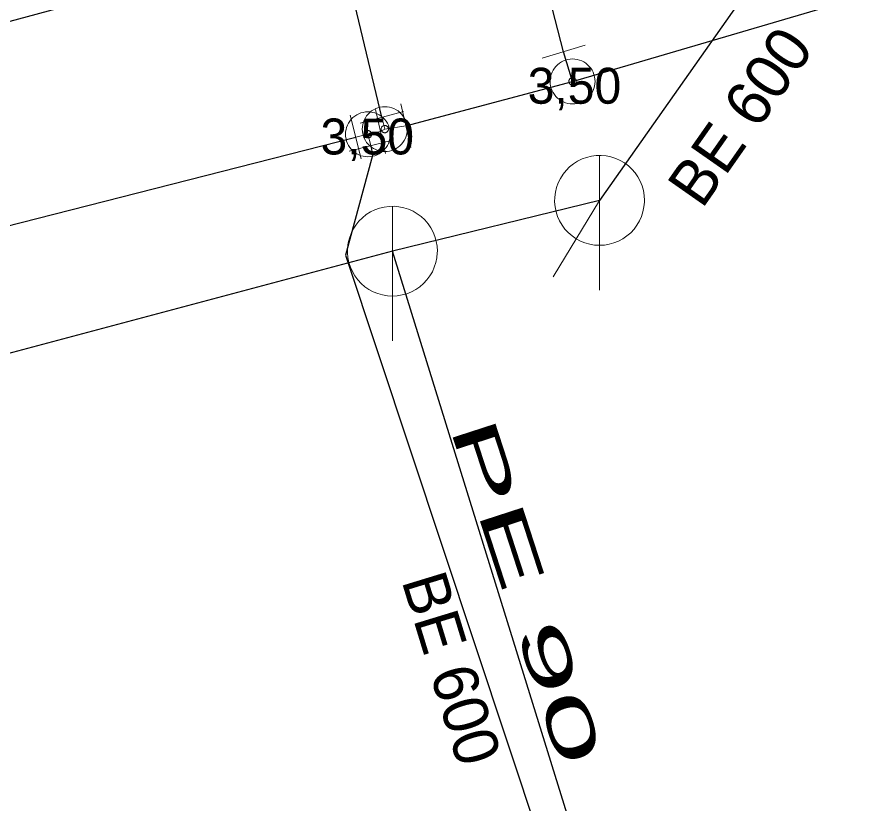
# Model space of a CAD drawing. Extents: x -682839 to -682312, y -994645 to -993949.
# Drawn here: x -682717.39 to -682698.3, y -994094.48 to -994076.96 of the extents above; entities that cross this region are included whole.
import ezdxf

# ---------------------------------------------------------------- set-up
doc = ezdxf.new("R2010")
doc.units = 0
doc.header["$LTSCALE"] = 0.4
doc.layers.add('1', color=7, linetype='Continuous')
for name, color, linetype, lineweight in [('11', 7, 'Continuous', 13), ('14', 7, 'Continuous', 25), ('17', 7, 'Continuous', 25), ('22', 7, 'Continuous', 13), ('34', 7, 'Continuous', 13), ('47', 7, 'Continuous', 13)]:
    doc.layers.add(name, color=color, linetype=linetype, lineweight=lineweight)

msp = doc.modelspace()

# ---------------------------------------------------------------- linework, layer by layer
at = {"layer": '11'}
msp.add_line((-682705.46, -994082.739), (-682704.43, -994081.039), dxfattribs=at)
at = {"layer": '14'}
for p, q in [((-682699.67, -994074.27), (-682704.43, -994081.039)), ((-682704.43, -994081.039), (-682709.039, -994082.17)), ((-682709.039, -994082.17), (-682748.64, -994092.739)), ((-682703.07, -994101.399), (-682709.039, -994082.17))]:
    msp.add_line(p, q, dxfattribs=at)
at = {"layer": '14', "lineweight": 13}
for p, q in [((-682709.208, -994079.453), (-682708.739, -994079.377)), ((-682709.583, -994079.568), (-682709.519, -994079.82))]:
    msp.add_line(p, q, dxfattribs=at)
msp.add_lwpolyline([(-682709.855, -994079.629), (-682709.583, -994079.568), (-682709.307, -994079.505), (-682709.208, -994079.453), (-682709.273, -994079.188)], dxfattribs=at)
at = {"layer": '17'}
for p, q in [((-682705.23, -994077.73), (-682706.989, -994070.899)), ((-682709.273, -994079.188), (-682710.75, -994073.01)), ((-682705.03, -994078.39), (-682705.23, -994077.73)), ((-682708.739, -994079.377), (-682705.03, -994078.39))]:
    msp.add_line(p, q, dxfattribs=at)
for points in [[(-682473.55, -994045.57), (-682522.289, -994043.899), (-682529.616, -994044.905), (-682556.26, -994048.129), (-682661.506, -994061.932), (-682719.074, -994077.464), (-682816.699, -994104.109)], [(-682705.03, -994078.39), (-682696.77, -994075.96), (-682691.829, -994074.544), (-682685.35, -994072.597), (-682672.05, -994068.67), (-682644.92, -994063.19), (-682632.77, -994060.73)], [(-682788.97, -994100.714), (-682780.37, -994098.68), (-682746.43, -994089.07), (-682728.02, -994084.32), (-682718.061, -994081.728), (-682709.855, -994079.629)], [(-682709.519, -994079.82), (-682709.48, -994080.039), (-682710.079, -994082.26), (-682705.76, -994095.289), (-682710, -994096.699)]]:
    msp.add_lwpolyline(points, dxfattribs=at)
at = {"layer": '22'}
for p, q in [((-682704.43, -994083.039), (-682704.429, -994080.039)), ((-682709.039, -994084.17), (-682709.038, -994081.17))]:
    msp.add_line(p, q, dxfattribs=at)
for points in [[(-682703.43, -994081.039), (-682703.435, -994080.93), (-682703.453, -994080.822), (-682703.483, -994080.716), (-682703.523, -994080.615), (-682703.575, -994080.518), (-682703.637, -994080.428), (-682703.709, -994080.345), (-682703.789, -994080.271), (-682703.877, -994080.205), (-682703.971, -994080.15), (-682704.071, -994080.105), (-682704.176, -994080.072), (-682704.283, -994080.05), (-682704.392, -994080.04), (-682704.502, -994080.042), (-682704.61, -994080.056), (-682704.717, -994080.081), (-682704.82, -994080.118), (-682704.918, -994080.167), (-682705.01, -994080.225), (-682705.096, -994080.294), (-682705.173, -994080.371), (-682705.242, -994080.457), (-682705.301, -994080.549), (-682705.349, -994080.647), (-682705.386, -994080.75), (-682705.412, -994080.857), (-682705.426, -994080.965), (-682705.429, -994081.075), (-682705.419, -994081.184), (-682705.398, -994081.291), (-682705.364, -994081.395), (-682705.32, -994081.495), (-682705.265, -994081.59), (-682705.199, -994081.678), (-682705.125, -994081.758), (-682705.042, -994081.83), (-682704.952, -994081.892), (-682704.856, -994081.944), (-682704.754, -994081.985), (-682704.649, -994082.015), (-682704.541, -994082.033), (-682704.431, -994082.039), (-682704.322, -994082.033), (-682704.214, -994082.015), (-682704.109, -994081.986), (-682704.007, -994081.945), (-682703.91, -994081.893), (-682703.82, -994081.831), (-682703.737, -994081.76), (-682703.662, -994081.68), (-682703.597, -994081.592), (-682703.541, -994081.498), (-682703.497, -994081.398), (-682703.463, -994081.294), (-682703.441, -994081.186), (-682703.431, -994081.077)], [(-682708.039, -994082.17), (-682708.044, -994082.061), (-682708.062, -994081.953), (-682708.092, -994081.847), (-682708.132, -994081.746), (-682708.184, -994081.649), (-682708.246, -994081.559), (-682708.318, -994081.476), (-682708.398, -994081.402), (-682708.486, -994081.336), (-682708.58, -994081.281), (-682708.68, -994081.236), (-682708.785, -994081.203), (-682708.892, -994081.181), (-682709.001, -994081.171), (-682709.111, -994081.173), (-682709.219, -994081.187), (-682709.326, -994081.212), (-682709.429, -994081.249), (-682709.527, -994081.298), (-682709.619, -994081.356), (-682709.705, -994081.425), (-682709.782, -994081.502), (-682709.851, -994081.588), (-682709.91, -994081.68), (-682709.958, -994081.778), (-682709.995, -994081.881), (-682710.021, -994081.988), (-682710.035, -994082.096), (-682710.038, -994082.206), (-682710.028, -994082.315), (-682710.007, -994082.422), (-682709.973, -994082.526), (-682709.929, -994082.626), (-682709.874, -994082.721), (-682709.808, -994082.809), (-682709.734, -994082.889), (-682709.651, -994082.961), (-682709.561, -994083.023), (-682709.465, -994083.075), (-682709.363, -994083.116), (-682709.258, -994083.146), (-682709.15, -994083.164), (-682709.04, -994083.17), (-682708.931, -994083.164), (-682708.823, -994083.146), (-682708.718, -994083.117), (-682708.616, -994083.076), (-682708.519, -994083.024), (-682708.429, -994082.962), (-682708.346, -994082.891), (-682708.271, -994082.811), (-682708.206, -994082.723), (-682708.15, -994082.629), (-682708.106, -994082.529), (-682708.072, -994082.425), (-682708.05, -994082.317), (-682708.04, -994082.208)]]:
    msp.add_lwpolyline(points, close=True, dxfattribs=at)
at = {"layer": '34'}
for p, q in [((-682705.708, -994077.875), (-682704.751, -994077.585)), ((-682708.85, -994078.889), (-682708.628, -994079.864)), ((-682708.79, -994079.057), (-682709.755, -994079.317)), ((-682709.418, -994079.017), (-682709.196, -994079.992)), ((-682709.979, -994079.144), (-682709.731, -994080.113)), ((-682709.034, -994079.696), (-682710.003, -994079.942))]:
    msp.add_line(p, q, dxfattribs=at)
at = {"layer": '47'}
for points in [[(-682704.53, -994078.39), (-682704.533, -994078.338), (-682704.541, -994078.286), (-682704.555, -994078.236), (-682704.573, -994078.187), (-682704.597, -994078.14), (-682704.626, -994078.096), (-682704.659, -994078.056), (-682704.696, -994078.019), (-682704.736, -994077.986), (-682704.78, -994077.957), (-682704.827, -994077.933), (-682704.876, -994077.915), (-682704.926, -994077.901), (-682704.978, -994077.893), (-682705.03, -994077.89), (-682705.082, -994077.893), (-682705.134, -994077.901), (-682705.185, -994077.915), (-682705.233, -994077.933), (-682705.28, -994077.957), (-682705.324, -994077.986), (-682705.365, -994078.019), (-682705.402, -994078.056), (-682705.435, -994078.096), (-682705.463, -994078.14), (-682705.487, -994078.187), (-682705.506, -994078.236), (-682705.519, -994078.286), (-682705.527, -994078.338), (-682705.53, -994078.39), (-682705.527, -994078.442), (-682705.519, -994078.494), (-682705.506, -994078.545), (-682705.487, -994078.593), (-682705.463, -994078.64), (-682705.435, -994078.684), (-682705.402, -994078.725), (-682705.365, -994078.762), (-682705.324, -994078.795), (-682705.28, -994078.823), (-682705.233, -994078.847), (-682705.185, -994078.866), (-682705.134, -994078.879), (-682705.082, -994078.887), (-682705.03, -994078.89), (-682704.978, -994078.887), (-682704.926, -994078.879), (-682704.876, -994078.866), (-682704.827, -994078.847), (-682704.78, -994078.823), (-682704.736, -994078.795), (-682704.696, -994078.762), (-682704.659, -994078.725), (-682704.626, -994078.684), (-682704.597, -994078.64), (-682704.573, -994078.593), (-682704.555, -994078.545), (-682704.541, -994078.494), (-682704.533, -994078.442)], [(-682704.948, -994078.39), (-682704.948, -994078.381), (-682704.95, -994078.373), (-682704.952, -994078.365), (-682704.955, -994078.357), (-682704.959, -994078.349), (-682704.964, -994078.342), (-682704.969, -994078.335), (-682704.975, -994078.329), (-682704.982, -994078.324), (-682704.989, -994078.319), (-682704.997, -994078.315), (-682705.005, -994078.312), (-682705.013, -994078.31), (-682705.021, -994078.308), (-682705.03, -994078.308), (-682705.039, -994078.308), (-682705.047, -994078.31), (-682705.055, -994078.312), (-682705.063, -994078.315), (-682705.071, -994078.319), (-682705.078, -994078.324), (-682705.085, -994078.329), (-682705.091, -994078.335), (-682705.097, -994078.342), (-682705.101, -994078.349), (-682705.105, -994078.357), (-682705.108, -994078.365), (-682705.11, -994078.373), (-682705.112, -994078.381), (-682705.112, -994078.39), (-682705.112, -994078.399), (-682705.11, -994078.407), (-682705.108, -994078.415), (-682705.105, -994078.423), (-682705.101, -994078.431), (-682705.097, -994078.438), (-682705.091, -994078.445), (-682705.085, -994078.451), (-682705.078, -994078.457), (-682705.071, -994078.461), (-682705.063, -994078.465), (-682705.055, -994078.468), (-682705.047, -994078.47), (-682705.039, -994078.472), (-682705.03, -994078.472), (-682705.021, -994078.472), (-682705.013, -994078.47), (-682705.005, -994078.468), (-682704.997, -994078.465), (-682704.989, -994078.461), (-682704.982, -994078.457), (-682704.975, -994078.451), (-682704.969, -994078.445), (-682704.964, -994078.438), (-682704.959, -994078.431), (-682704.955, -994078.423), (-682704.952, -994078.415), (-682704.95, -994078.407), (-682704.948, -994078.399)], [(-682709.083, -994079.568), (-682709.086, -994079.516), (-682709.094, -994079.463), (-682709.108, -994079.414), (-682709.125, -994079.365), (-682709.15, -994079.318), (-682709.179, -994079.274), (-682709.212, -994079.233), (-682709.249, -994079.196), (-682709.289, -994079.164), (-682709.333, -994079.135), (-682709.38, -994079.11), (-682709.429, -994079.093), (-682709.478, -994079.079), (-682709.531, -994079.071), (-682709.583, -994079.068), (-682709.635, -994079.071), (-682709.687, -994079.079), (-682709.738, -994079.093), (-682709.786, -994079.11), (-682709.833, -994079.135), (-682709.877, -994079.164), (-682709.918, -994079.196), (-682709.955, -994079.233), (-682709.988, -994079.274), (-682710.016, -994079.318), (-682710.04, -994079.365), (-682710.059, -994079.414), (-682710.071, -994079.463), (-682710.08, -994079.516), (-682710.083, -994079.568), (-682710.08, -994079.62), (-682710.071, -994079.672), (-682710.059, -994079.723), (-682710.04, -994079.771), (-682710.016, -994079.818), (-682709.988, -994079.862), (-682709.955, -994079.902), (-682709.918, -994079.94), (-682709.877, -994079.973), (-682709.833, -994080), (-682709.786, -994080.025), (-682709.738, -994080.044), (-682709.687, -994080.056), (-682709.635, -994080.065), (-682709.583, -994080.068), (-682709.531, -994080.065), (-682709.478, -994080.056), (-682709.429, -994080.044), (-682709.38, -994080.025), (-682709.333, -994080), (-682709.289, -994079.973), (-682709.249, -994079.94), (-682709.212, -994079.902), (-682709.179, -994079.862), (-682709.15, -994079.818), (-682709.125, -994079.771), (-682709.108, -994079.723), (-682709.094, -994079.672), (-682709.086, -994079.62)], [(-682708.708, -994079.453), (-682708.711, -994079.401), (-682708.719, -994079.348), (-682708.733, -994079.299), (-682708.75, -994079.25), (-682708.775, -994079.203), (-682708.804, -994079.159), (-682708.837, -994079.119), (-682708.874, -994079.081), (-682708.914, -994079.049), (-682708.958, -994079.02), (-682709.005, -994078.995), (-682709.054, -994078.978), (-682709.103, -994078.964), (-682709.156, -994078.956), (-682709.208, -994078.953), (-682709.26, -994078.956), (-682709.312, -994078.964), (-682709.363, -994078.978), (-682709.411, -994078.995), (-682709.458, -994079.02), (-682709.502, -994079.049), (-682709.543, -994079.081), (-682709.58, -994079.119), (-682709.613, -994079.159), (-682709.641, -994079.203), (-682709.665, -994079.25), (-682709.684, -994079.299), (-682709.696, -994079.348), (-682709.705, -994079.401), (-682709.708, -994079.453), (-682709.705, -994079.505), (-682709.696, -994079.557), (-682709.684, -994079.608), (-682709.665, -994079.656), (-682709.641, -994079.703), (-682709.613, -994079.747), (-682709.58, -994079.788), (-682709.543, -994079.825), (-682709.502, -994079.858), (-682709.458, -994079.886), (-682709.411, -994079.91), (-682709.363, -994079.929), (-682709.312, -994079.941), (-682709.26, -994079.95), (-682709.208, -994079.953), (-682709.156, -994079.95), (-682709.103, -994079.941), (-682709.054, -994079.929), (-682709.005, -994079.91), (-682708.958, -994079.886), (-682708.914, -994079.858), (-682708.874, -994079.825), (-682708.837, -994079.788), (-682708.804, -994079.747), (-682708.775, -994079.703), (-682708.75, -994079.656), (-682708.733, -994079.608), (-682708.719, -994079.557), (-682708.711, -994079.505)], [(-682709.125, -994079.453), (-682709.125, -994079.444), (-682709.128, -994079.436), (-682709.13, -994079.428), (-682709.133, -994079.419), (-682709.137, -994079.412), (-682709.142, -994079.405), (-682709.147, -994079.397), (-682709.152, -994079.392), (-682709.16, -994079.387), (-682709.167, -994079.382), (-682709.174, -994079.378), (-682709.183, -994079.375), (-682709.191, -994079.373), (-682709.199, -994079.37), (-682709.208, -994079.37), (-682709.217, -994079.37), (-682709.225, -994079.373), (-682709.233, -994079.375), (-682709.241, -994079.378), (-682709.249, -994079.382), (-682709.255, -994079.387), (-682709.263, -994079.392), (-682709.269, -994079.397), (-682709.275, -994079.405), (-682709.279, -994079.412), (-682709.282, -994079.419), (-682709.286, -994079.428), (-682709.288, -994079.436), (-682709.29, -994079.444), (-682709.29, -994079.453), (-682709.29, -994079.462), (-682709.288, -994079.47), (-682709.286, -994079.478), (-682709.282, -994079.486), (-682709.279, -994079.494), (-682709.275, -994079.5), (-682709.269, -994079.508), (-682709.263, -994079.514), (-682709.255, -994079.52), (-682709.249, -994079.524), (-682709.241, -994079.527), (-682709.233, -994079.531), (-682709.225, -994079.532), (-682709.217, -994079.535), (-682709.208, -994079.535), (-682709.199, -994079.535), (-682709.191, -994079.532), (-682709.183, -994079.531), (-682709.174, -994079.527), (-682709.167, -994079.524), (-682709.16, -994079.52), (-682709.152, -994079.514), (-682709.147, -994079.508), (-682709.142, -994079.5), (-682709.137, -994079.494), (-682709.133, -994079.486), (-682709.13, -994079.478), (-682709.128, -994079.47), (-682709.125, -994079.462)], [(-682709.5, -994079.568), (-682709.5, -994079.559), (-682709.503, -994079.551), (-682709.505, -994079.543), (-682709.508, -994079.534), (-682709.512, -994079.527), (-682709.517, -994079.52), (-682709.522, -994079.512), (-682709.527, -994079.507), (-682709.535, -994079.502), (-682709.542, -994079.497), (-682709.549, -994079.493), (-682709.558, -994079.49), (-682709.566, -994079.488), (-682709.574, -994079.485), (-682709.583, -994079.485), (-682709.592, -994079.485), (-682709.6, -994079.488), (-682709.608, -994079.49), (-682709.616, -994079.493), (-682709.624, -994079.497), (-682709.63, -994079.502), (-682709.638, -994079.507), (-682709.644, -994079.512), (-682709.65, -994079.52), (-682709.654, -994079.527), (-682709.657, -994079.534), (-682709.661, -994079.543), (-682709.663, -994079.551), (-682709.665, -994079.559), (-682709.665, -994079.568), (-682709.665, -994079.576), (-682709.663, -994079.585), (-682709.661, -994079.593), (-682709.657, -994079.601), (-682709.654, -994079.608), (-682709.65, -994079.615), (-682709.644, -994079.623), (-682709.638, -994079.629), (-682709.63, -994079.635), (-682709.624, -994079.639), (-682709.616, -994079.642), (-682709.608, -994079.646), (-682709.6, -994079.647), (-682709.592, -994079.65), (-682709.583, -994079.65), (-682709.574, -994079.65), (-682709.566, -994079.647), (-682709.558, -994079.646), (-682709.549, -994079.642), (-682709.542, -994079.639), (-682709.535, -994079.635), (-682709.527, -994079.629), (-682709.522, -994079.623), (-682709.517, -994079.615), (-682709.512, -994079.608), (-682709.508, -994079.601), (-682709.505, -994079.593), (-682709.503, -994079.585), (-682709.5, -994079.576)]]:
    msp.add_lwpolyline(points, close=True, dxfattribs=at)

# ---------------------------------------------------------------- texts
at = {"layer": '1'}
for rotation, p in [(55, (-682702.15, -994081.25)), (287, (-682708.84, -994089.508))]:
    msp.add_text('BE 600', height=1, rotation=rotation, dxfattribs=at).set_placement(p)
for p in [(-682706.029, -994078.887), (-682710.639, -994080.017)]:
    msp.add_text('3,50', height=0.8, dxfattribs=at).set_placement(p)
at = {"layer": '1', "width": 2.2}
msp.add_text('PE 90 ', height=1, rotation=288, dxfattribs=at).set_placement((-682707.771, -994086.091))

doc.saveas('drawing.dxf')
